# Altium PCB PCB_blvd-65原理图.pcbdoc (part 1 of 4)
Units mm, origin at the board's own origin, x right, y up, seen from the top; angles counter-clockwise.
Board outline 317.5 x 107.96 mm, 2 copper layers (Top Layer, Bottom Layer); 180 components, 111 nets, 404 pads, 231 vias.
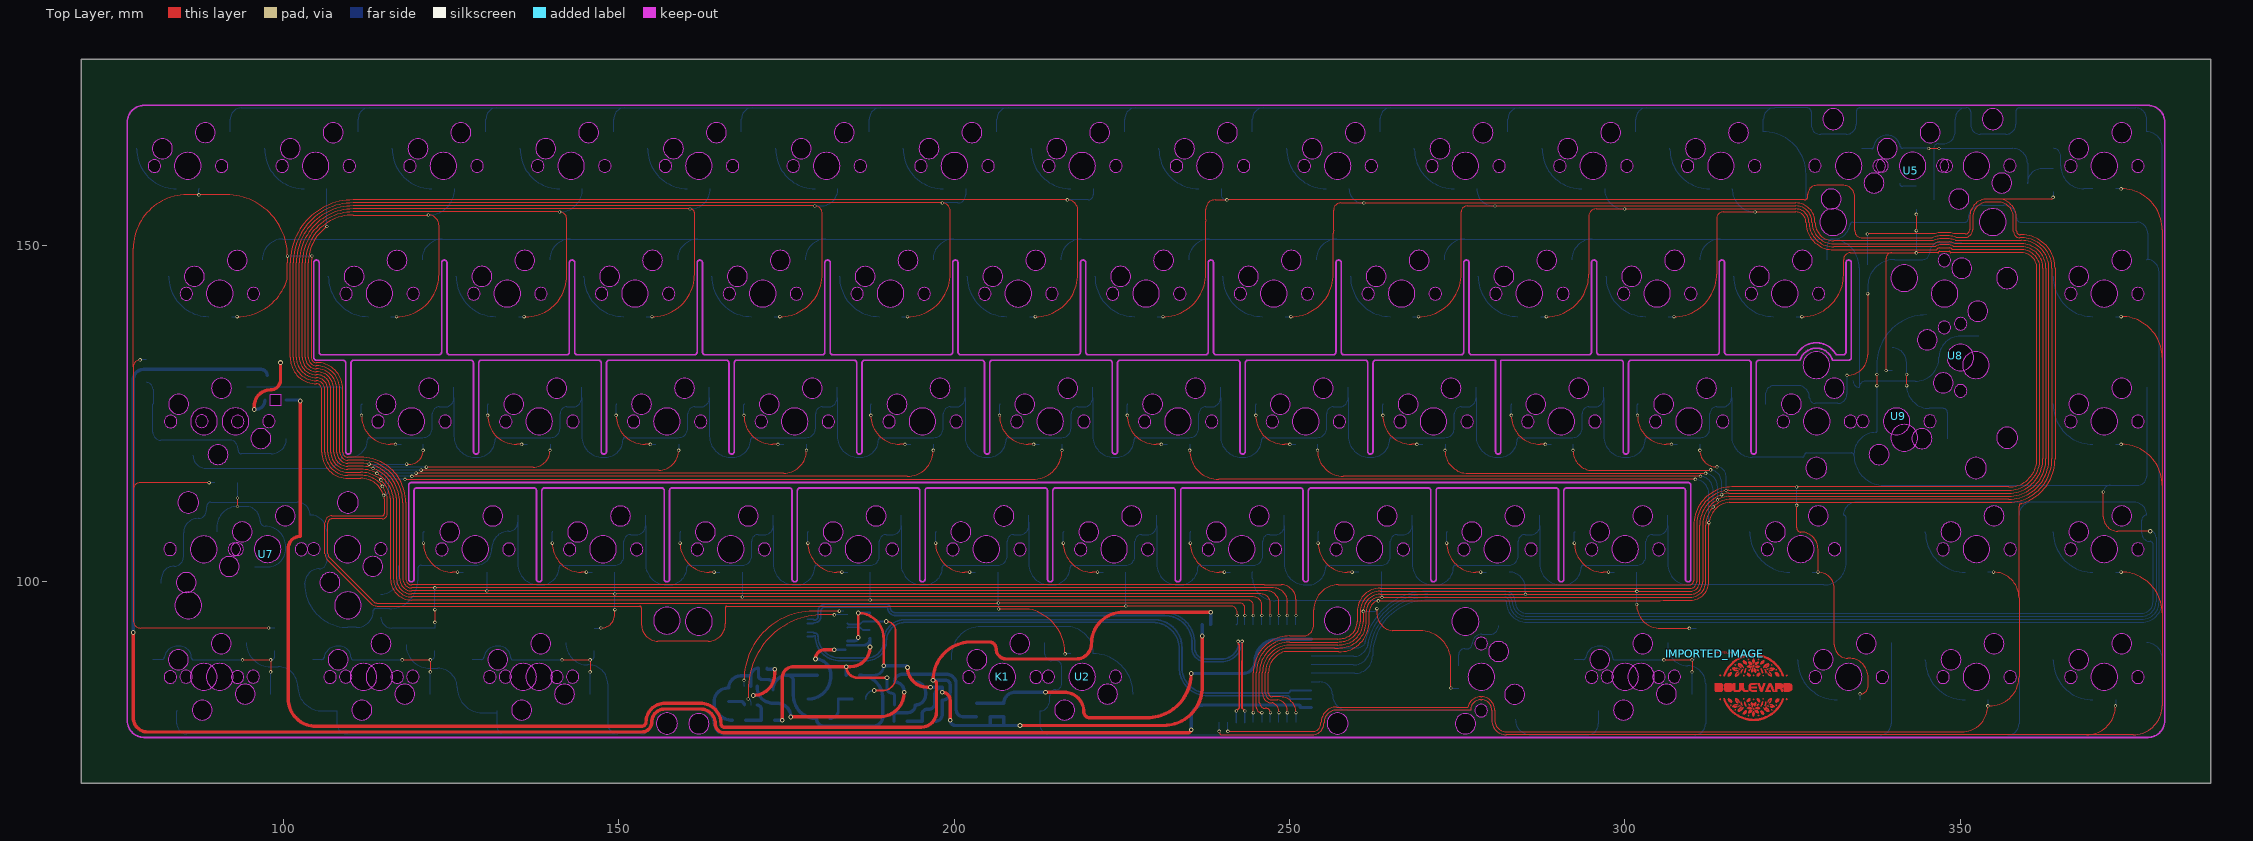
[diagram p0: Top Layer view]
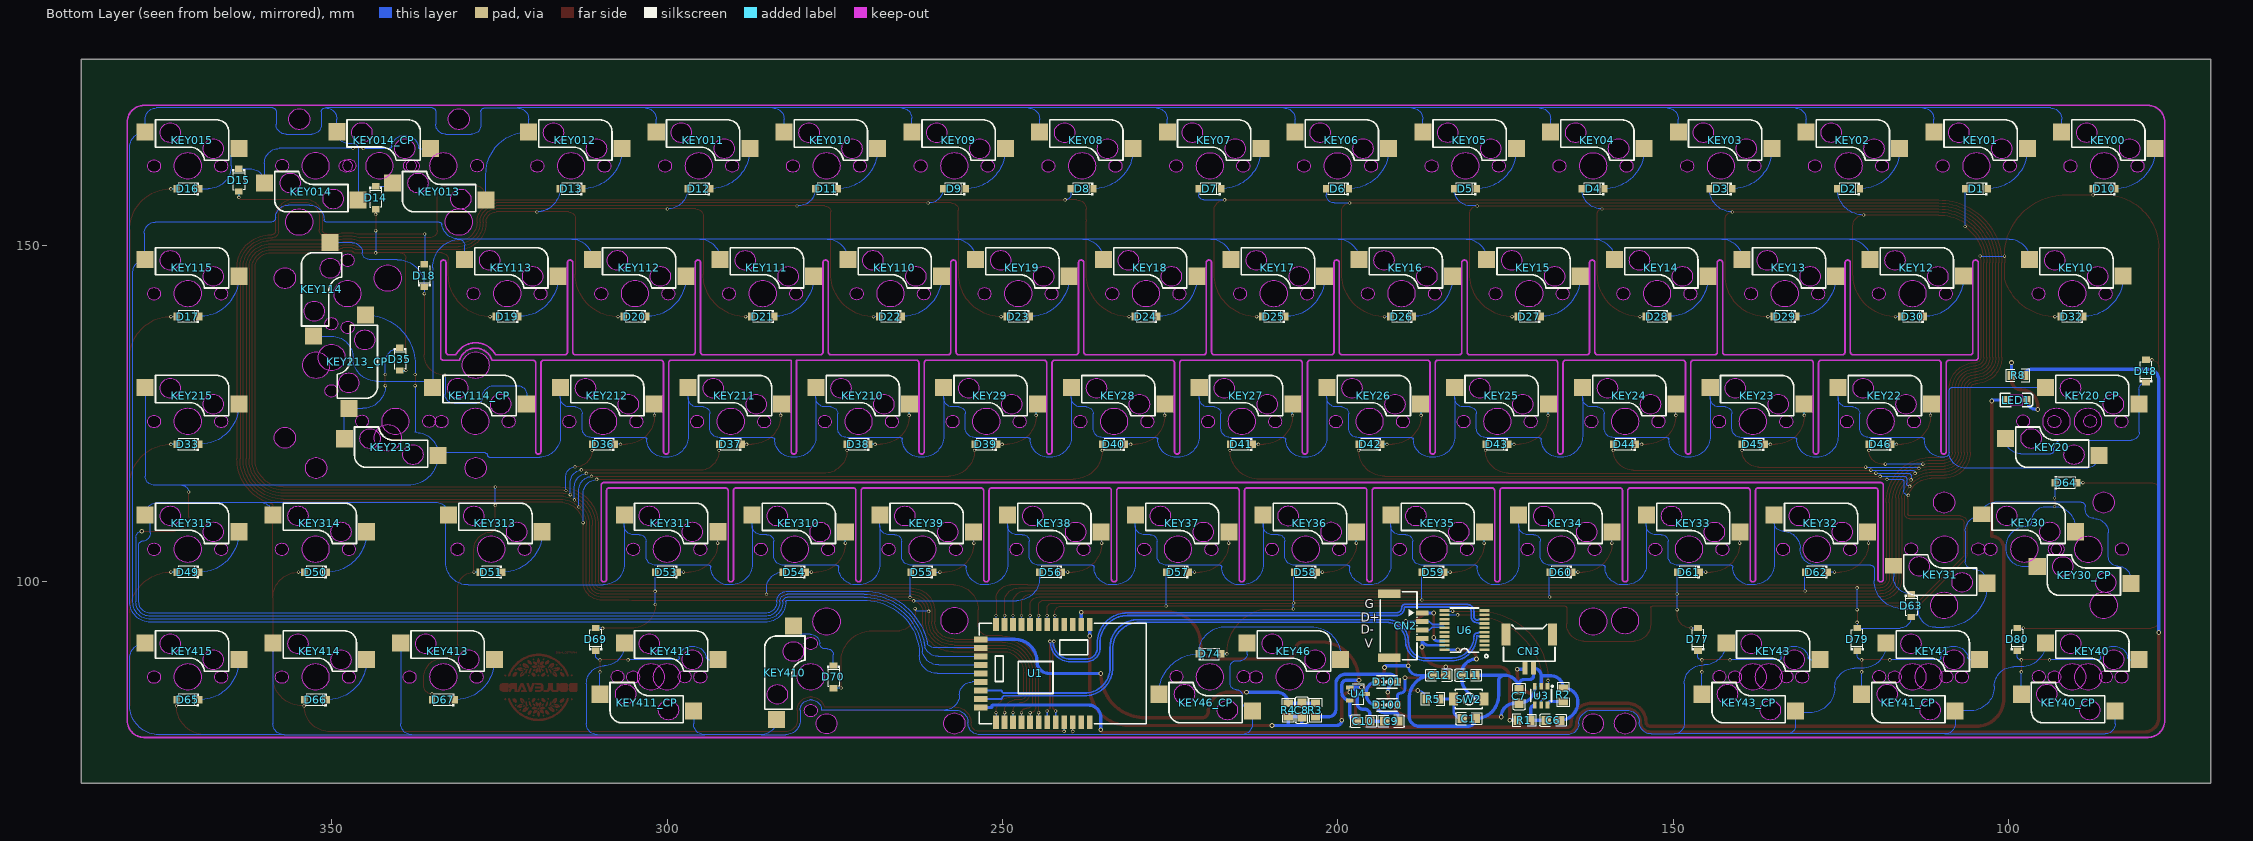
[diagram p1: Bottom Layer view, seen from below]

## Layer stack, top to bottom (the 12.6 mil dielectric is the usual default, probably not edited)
Top Layer: signal copper (thickness not stored)
Dielectric: dielectric 0.32, FR-4, Dk 4.8
Bottom Layer: signal copper (thickness not stored)

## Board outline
387.35,69.85 69.85,69.85 69.85,177.805 387.35,177.805

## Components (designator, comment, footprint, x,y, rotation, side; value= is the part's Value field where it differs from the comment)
C1 "47pF" C0805 180.467,79.502 r0 bottom
C6 "1uF" C0805 167.894,79.248 r0 bottom
C7 "10uF" C0805 172.974,82.804 r270 bottom
C8 "10nF" C0805 205.359,80.772 r270 bottom
C9 "1uF" C0805 192.024,79.121 r180 bottom
C10 "1uF" C0805 196.215,79.121 r0 bottom
C11 "100nF" C0805 180.594,85.979 r0 bottom
C12 "100nF" C0805 184.912,85.979 r180 bottom
CN2 "537800470" CONN-TH_4P-P1.25_537800470 189.865,93.345 r270 bottom
CN3 "537800270" CONN-SMD_2P-P1.25_53780-0X70 171.45,89.535 r0 bottom
D1 "1N4148W_C115103" SOD-123_L2.8-W1.8-LS3.7-RD 104.775,158.496 r0 bottom
D2 "1N4148W_C115103" SOD-123_L2.8-W1.8-LS3.7-RD 123.825,158.496 r0 bottom
D3 "1N4148W_C115103" SOD-123_L2.8-W1.8-LS3.7-RD 142.875,158.496 r0 bottom
D4 "1N4148W_C115103" SOD-123_L2.8-W1.8-LS3.7-RD 161.925,158.496 r0 bottom
D5 "1N4148W_C115103" SOD-123_L2.8-W1.8-LS3.7-RD 180.975,158.496 r0 bottom
D6 "1N4148W_C115103" SOD-123_L2.8-W1.8-LS3.7-RD 200.025,158.496 r0 bottom
D7 "1N4148W_C115103" SOD-123_L2.8-W1.8-LS3.7-RD 219.075,158.496 r0 bottom
D8 "1N4148W_C115103" SOD-123_L2.8-W1.8-LS3.7-RD 238.125,158.496 r0 bottom
D9 "1N4148W_C115103" SOD-123_L2.8-W1.8-LS3.7-RD 257.175,158.496 r0 bottom
D10 "1N4148W_C115103" SOD-123_L2.8-W1.8-LS3.7-RD 85.725,158.496 r0 bottom
D11 "1N4148W_C115103" SOD-123_L2.8-W1.8-LS3.7-RD 276.225,158.496 r0 bottom
D12 "1N4148W_C115103" SOD-123_L2.8-W1.8-LS3.7-RD 295.275,158.496 r0 bottom
D13 "1N4148W_C115103" SOD-123_L2.8-W1.8-LS3.7-RD 314.325,158.496 r0 bottom
D14 "1N4148W_C115103" SOD-123_L2.8-W1.8-LS3.7-RD 343.463,157.164 r270 bottom
D15 "1N4148W_C115103" SOD-123_L2.8-W1.8-LS3.7-RD 363.874,159.791 r270 bottom
D16 "1N4148W_C115103" SOD-123_L2.8-W1.8-LS3.7-RD 371.475,158.496 r0 bottom
D17 "1N4148W_C115103" SOD-123_L2.8-W1.8-LS3.7-RD 371.475,139.446 r0 bottom
D18 "1N4148W_C115103" SOD-123_L2.8-W1.8-LS3.7-RD 336.207,145.574 r90 bottom
D19 "1N4148W_C115103" SOD-123_L2.8-W1.8-LS3.7-RD 323.85,139.446 r0 bottom
D20 "1N4148W_C115103" SOD-123_L2.8-W1.8-LS3.7-RD 304.8,139.446 r0 bottom
D21 "1N4148W_C115103" SOD-123_L2.8-W1.8-LS3.7-RD 285.75,139.446 r0 bottom
D22 "1N4148W_C115103" SOD-123_L2.8-W1.8-LS3.7-RD 266.7,139.446 r0 bottom
D23 "1N4148W_C115103" SOD-123_L2.8-W1.8-LS3.7-RD 247.65,139.446 r0 bottom
D24 "1N4148W_C115103" SOD-123_L2.8-W1.8-LS3.7-RD 228.6,139.446 r0 bottom
D25 "1N4148W_C115103" SOD-123_L2.8-W1.8-LS3.7-RD 209.55,139.446 r0 bottom
D26 "1N4148W_C115103" SOD-123_L2.8-W1.8-LS3.7-RD 190.5,139.446 r0 bottom
D27 "1N4148W_C115103" SOD-123_L2.8-W1.8-LS3.7-RD 171.45,139.446 r0 bottom
D28 "1N4148W_C115103" SOD-123_L2.8-W1.8-LS3.7-RD 152.4,139.446 r0 bottom
D29 "1N4148W_C115103" SOD-123_L2.8-W1.8-LS3.7-RD 133.35,139.446 r0 bottom
D30 "1N4148W_C115103" SOD-123_L2.8-W1.8-LS3.7-RD 114.3,139.446 r0 bottom
D32 "1N4148W_C115103" SOD-123_L2.8-W1.8-LS3.7-RD 90.551,139.446 r0 bottom
D33 "1N4148W_C115103" SOD-123_L2.8-W1.8-LS3.7-RD 371.475,120.396 r0 bottom
D35 "1N4148W_C115103" SOD-123_L2.8-W1.8-LS3.7-RD 339.852,133.096 r270 bottom
D36 "1N4148W_C115103" SOD-123_L2.8-W1.8-LS3.7-RD 309.499,120.396 r0 bottom
D37 "1N4148W_C115103" SOD-123_L2.8-W1.8-LS3.7-RD 290.576,120.396 r0 bottom
D38 "1N4148W_C115103" SOD-123_L2.8-W1.8-LS3.7-RD 271.526,120.396 r0 bottom
D39 "1N4148W_C115103" SOD-123_L2.8-W1.8-LS3.7-RD 252.476,120.396 r0 bottom
D40 "1N4148W_C115103" SOD-123_L2.8-W1.8-LS3.7-RD 233.426,120.396 r0 bottom
D41 "1N4148W_C115103" SOD-123_L2.8-W1.8-LS3.7-RD 214.376,120.396 r0 bottom
D42 "1N4148W_C115103" SOD-123_L2.8-W1.8-LS3.7-RD 195.199,120.396 r0 bottom
D43 "1N4148W_C115103" SOD-123_L2.8-W1.8-LS3.7-RD 176.276,120.396 r0 bottom
D44 "1N4148W_C115103" SOD-123_L2.8-W1.8-LS3.7-RD 157.226,120.396 r0 bottom
D45 "1N4148W_C115103" SOD-123_L2.8-W1.8-LS3.7-RD 138.049,120.396 r0 bottom
D46 "1N4148W_C115103" SOD-123_L2.8-W1.8-LS3.7-RD 119.126,120.396 r0 bottom
D48 "1N4148W_C115103" SOD-123_L2.8-W1.8-LS3.7-RD 79.502,131.318 r90 bottom
D49 "1N4148W_C115103" SOD-123_L2.8-W1.8-LS3.7-RD 371.475,101.346 r0 bottom
D50 "1N4148W_C115103" SOD-123_L2.8-W1.8-LS3.7-RD 352.425,101.346 r0 bottom
D51 "1N4148W_C115103" SOD-123_L2.8-W1.8-LS3.7-RD 326.263,101.346 r0 bottom
D53 "1N4148W_C115103" SOD-123_L2.8-W1.8-LS3.7-RD 300.101,101.346 r0 bottom
D54 "1N4148W_C115103" SOD-123_L2.8-W1.8-LS3.7-RD 281.051,101.346 r0 bottom
D55 "1N4148W_C115103" SOD-123_L2.8-W1.8-LS3.7-RD 262.001,101.346 r0 bottom
D56 "1N4148W_C115103" SOD-123_L2.8-W1.8-LS3.7-RD 242.824,101.346 r0 bottom
D57 "1N4148W_C115103" SOD-123_L2.8-W1.8-LS3.7-RD 223.901,101.346 r0 bottom
D58 "1N4148W_C115103" SOD-123_L2.8-W1.8-LS3.7-RD 204.846,101.346 r0 bottom
D59 "1N4148W_C115103" SOD-123_L2.8-W1.8-LS3.7-RD 185.796,101.346 r0 bottom
D60 "1N4148W_C115103" SOD-123_L2.8-W1.8-LS3.7-RD 166.746,101.346 r0 bottom
D61 "1N4148W_C115103" SOD-123_L2.8-W1.8-LS3.7-RD 147.696,101.346 r0 bottom
D62 "1N4148W_C115103" SOD-123_L2.8-W1.8-LS3.7-RD 128.646,101.346 r0 bottom
D63 "1N4148W_C115103" SOD-123_L2.8-W1.8-LS3.7-RD 114.497,96.344 r270 bottom
D64 "1N4148W_C115103" SOD-123_L2.8-W1.8-LS3.7-RD 91.44,114.681 r180 bottom
D65 "1N4148W_C115103" SOD-123_L2.8-W1.8-LS3.7-RD 371.475,82.296 r0 bottom
D66 "1N4148W_C115103" SOD-123_L2.8-W1.8-LS3.7-RD 352.425,82.296 r0 bottom
D67 "1N4148W_C115103" SOD-123_L2.8-W1.8-LS3.7-RD 333.375,82.296 r0 bottom
D69 "1N4148W_C115103" SOD-123_L2.8-W1.8-LS3.7-RD 310.642,91.313 r90 bottom
D70 "1N4148W_C115103" SOD-123_L2.8-W1.8-LS3.7-RD 275.209,85.725 r270 bottom
D74 "1N4148W_C115103" SOD-123_L2.8-W1.8-LS3.7-RD 219.075,89.154 r180 bottom
D77 "1N4148W_C115103" SOD-123_L2.8-W1.8-LS3.7-RD 146.304,91.313 r90 bottom
D79 "1N4148W_C115103" SOD-123_L2.8-W1.8-LS3.7-RD 122.555,91.313 r90 bottom
D80 "1N4148W_C115103" SOD-123_L2.8-W1.8-LS3.7-RD 98.679,91.313 r90 bottom
D100 "B5819WL" SOD-123F_L2.8-W1.8-LS3.7-RD 192.659,81.534 r180 bottom
D101 "B5819WL" SOD-123F_L2.8-W1.8-LS3.7-RD 192.659,84.963 r180 bottom
IMPORTED_IMAGE "IMPORTED_IMAGE" IMPORTED_IMAGE#1 313.437,89.153 r0 top
IMPORTED_IMAGE "IMPORTED_IMAGE" IMPORTED_IMAGE#2 313.437,89.153 r0 top
K1 "6.25U卫星轴 COPY" 6.25U卫星轴 207.167,85.726 r180 top
KEY00 "KEY00" 凯华轴座无灯#1 85.725,161.926 r0 top
KEY01 "KEY01" 凯华轴座无灯#1 104.775,161.926 r0 top
KEY02 "凯华轴座无灯 COPY" 凯华轴座无灯#1 123.825,161.926 r0 top
KEY03 "凯华轴座无灯 COPY" 凯华轴座无灯#1 142.875,161.926 r0 top
KEY04 "凯华轴座无灯 COPY" 凯华轴座无灯#1 161.925,161.926 r0 top
KEY05 "凯华轴座无灯 COPY" 凯华轴座无灯#1 180.974,161.926 r0 top
KEY06 "凯华轴座无灯 COPY" 凯华轴座无灯#1 200.023,161.926 r0 top
KEY07 "凯华轴座无灯 COPY" 凯华轴座无灯#1 219.075,161.926 r0 top
KEY08 "凯华轴座无灯 COPY" 凯华轴座无灯#1 238.125,161.926 r0 top
KEY09 "凯华轴座无灯 COPY" 凯华轴座无灯#1 257.175,161.926 r0 top
KEY010 "凯华轴座无灯 COPY" 凯华轴座无灯#1 276.225,161.925 r0 top
KEY10 "KEY00" 凯华轴座无灯#1 90.488,142.876 r0 top
KEY011 "凯华轴座无灯 COPY" 凯华轴座无灯#1 295.275,161.926 r0 top
KEY012 "凯华轴座无灯 COPY" 凯华轴座无灯#1 314.325,161.925 r0 top
KEY12 "凯华轴座无灯 COPY" 凯华轴座无灯#1 114.3,142.876 r0 top
KEY013 "凯华轴座无灯 COPY" 凯华轴座无灯#1 333.375,161.925 r180 top
KEY13 "凯华轴座无灯 COPY" 凯华轴座无灯#1 133.35,142.875 r0 top
KEY14 "凯华轴座无灯 COPY" 凯华轴座无灯#1 152.4,142.875 r0 top
KEY014 "凯华轴座无灯 COPY" 凯华轴座无灯#1 352.425,161.93 r180 top
KEY014_CP "凯华轴座无灯 COPY" 凯华轴座无灯#1 342.9,161.93 r0 top
KEY15 "凯华轴座无灯 COPY" 凯华轴座无灯#1 171.45,142.875 r0 top
KEY015 "凯华轴座无灯 COPY" 凯华轴座无灯#1 371.475,161.926 r0 top
KEY16 "凯华轴座无灯 COPY" 凯华轴座无灯#1 190.5,142.875 r0 top
KEY17 "凯华轴座无灯 COPY" 凯华轴座无灯#1 209.55,142.875 r0 top
KEY18 "凯华轴座无灯 COPY" 凯华轴座无灯#1 228.6,142.875 r0 top
KEY19 "凯华轴座无灯 COPY" 凯华轴座无灯#1 247.65,142.875 r0 top
KEY20 "KEY00" 凯华轴座无灯#1 92.837,123.825 r180 top
KEY20_CP "KEY00" 凯华轴座无灯#1 88.138,123.825 r0 top
KEY22 "凯华轴座无灯 COPY" 凯华轴座无灯#1 119.063,123.815 r0 top
KEY23 "凯华轴座无灯 COPY" 凯华轴座无灯#1 138.113,123.815 r0 top
KEY24 "凯华轴座无灯 COPY" 凯华轴座无灯#1 157.163,123.815 r0 top
KEY25 "凯华轴座无灯 COPY" 凯华轴座无灯#1 176.213,123.815 r0 top
KEY26 "凯华轴座无灯 COPY" 凯华轴座无灯#1 195.263,123.815 r0 top
KEY27 "凯华轴座无灯 COPY" 凯华轴座无灯#1 214.313,123.815 r0 top
KEY28 "凯华轴座无灯 COPY" 凯华轴座无灯#1 233.363,123.815 r0 top
KEY29 "凯华轴座无灯 COPY" 凯华轴座无灯#1 252.413,123.815 r0 top
KEY30 "KEY00" 凯华轴座无灯#2 97.631,104.776 r0 top
KEY30_CP "KEY00" 凯华轴座无灯#1 88.106,104.745 r180 top
KEY31 "KEY01" 凯华轴座无灯#3 109.533,104.765 r180 top
KEY32 "凯华轴座无灯 COPY" 凯华轴座无灯#1 128.583,104.765 r0 top
KEY33 "凯华轴座无灯 COPY" 凯华轴座无灯#1 147.633,104.765 r0 top
KEY34 "凯华轴座无灯 COPY" 凯华轴座无灯#1 166.683,104.765 r0 top
KEY35 "凯华轴座无灯 COPY" 凯华轴座无灯#1 185.733,104.765 r0 top
KEY36 "凯华轴座无灯 COPY" 凯华轴座无灯#1 204.783,104.765 r0 top
KEY37 "凯华轴座无灯 COPY" 凯华轴座无灯#1 223.833,104.765 r0 top
KEY38 "凯华轴座无灯 COPY" 凯华轴座无灯#1 242.883,104.765 r0 top
KEY39 "凯华轴座无灯 COPY" 凯华轴座无灯#1 261.933,104.765 r0 top
KEY40 "KEY00" 凯华轴座无灯#1 88.106,85.726 r0 top
KEY40_CP "KEY00" 凯华轴座无灯#1 90.488,85.726 r180 top
KEY41 "KEY01" 凯华轴座无灯#1 111.917,85.726 r0 top
KEY41_CP "KEY01" 凯华轴座无灯#1 114.3,85.726 r180 top
KEY43 "凯华轴座无灯 COPY" 凯华轴座无灯#1 135.731,85.726 r0 top
KEY43_CP "凯华轴座无灯 COPY" 凯华轴座无灯#1 138.113,85.726 r180 top
KEY46 "凯华轴座无灯 COPY" 凯华轴座无灯#1 207.167,85.726 r0 top
KEY46_CP "凯华轴座无灯 COPY" 凯华轴座无灯#1 219.075,85.726 r180 top
KEY110 "凯华轴座无灯 COPY" 凯华轴座无灯#1 266.7,142.875 r0 top
KEY111 "凯华轴座无灯 COPY" 凯华轴座无灯#1 285.75,142.875 r0 top
KEY112 "凯华轴座无灯 COPY" 凯华轴座无灯#1 304.8,142.875 r0 top
KEY113 "凯华轴座无灯 COPY" 凯华轴座无灯#1 323.85,142.875 r0 top
KEY114 "凯华轴座无灯 COPY" 凯华轴座无灯#4 347.665,142.872 r270 top
KEY114_CP "凯华轴座无灯 COPY" 凯华轴座无灯#1 328.612,123.825 r0 top
KEY115 "凯华轴座无灯 COPY" 凯华轴座无灯#1 371.475,142.875 r0 top
KEY210 "凯华轴座无灯 COPY" 凯华轴座无灯#1 271.463,123.815 r0 top
KEY211 "凯华轴座无灯 COPY" 凯华轴座无灯#1 290.513,123.815 r0 top
KEY212 "凯华轴座无灯 COPY" 凯华轴座无灯#1 309.563,123.815 r0 top
KEY213 "凯华轴座无灯 COPY" 凯华轴座无灯#1 340.519,123.822 r180 top
KEY213_CP "凯华轴座无灯 COPY" 凯华轴座无灯#4 350.044,133.347 r90 top
KEY215 "凯华轴座无灯 COPY" 凯华轴座无灯#1 371.475,123.825 r0 top
KEY310 "凯华轴座无灯 COPY" 凯华轴座无灯#1 280.983,104.765 r0 top
KEY311 "凯华轴座无灯 COPY" 凯华轴座无灯#1 300.037,104.776 r0 top
KEY313 "凯华轴座无灯 COPY" 凯华轴座无灯#1 326.232,104.775 r0 top
KEY314 "凯华轴座无灯 COPY" 凯华轴座无灯#1 352.425,104.775 r0 top
KEY315 "凯华轴座无灯 COPY" 凯华轴座无灯#1 371.475,104.775 r0 top
KEY410 "凯华轴座无灯 COPY" 凯华轴座无灯#4 278.606,85.726 r270 top
KEY411 "凯华轴座无灯 COPY" 凯华轴座无灯#1 300.037,85.726 r0 top
KEY411_CP "凯华轴座无灯 COPY" 凯华轴座无灯#1 302.417,85.726 r180 top
KEY413 "凯华轴座无灯 COPY" 凯华轴座无灯#1 333.375,85.725 r0 top
KEY414 "凯华轴座无灯 COPY" 凯华轴座无灯#1 352.425,85.725 r0 top
KEY415 "凯华轴座无灯 COPY" 凯华轴座无灯#1 371.475,85.725 r0 top
LED1 "MHT151UBCT" LED-SMD_L3.2-W1.3-RD-EH2.1 98.806,127 r0 bottom
R1 "1Ω" R0805 172.212,79.248 r0 bottom
R2 "4.7K" R0805 166.37,83.058 r90 bottom
R3 "10MΩ" R0805 203.327,80.772 r270 bottom
R4 "2.2MΩ" R0805 207.391,80.772 r270 bottom
R5 "10K" R0805 185.801,82.423 r180 bottom
R8 "15Ω" R0805 98.552,130.683 r180 bottom
SW2 "TS-1088R-02026" SW-SMD_L3.9-W3.0-P4.45 180.467,82.423 r180 bottom
U1 "NRF52832 RF-BM-ND04" BULETM-SMD_NRF52832 245.11,86.233 r270 bottom
U2 "PCB卫星轴-7U COPY" PCB卫星轴-7U 219.075,85.726 r0 top
U3 "TP4057" SOT-23-6_L2.9-W1.6-P0.95-LS2.8-BR 169.672,82.931 r90 bottom
U4 "XC6206P332MR" SOT-23-3_L2.9-W1.6-P1.90-LS2.8-BR 196.977,83.185 r0 bottom
U5 "PCB卫星轴2U COPY" 卫星轴2U#1 342.631,161.183 r0 top
U6 "CH552T" TSSOP-20_L6.5-W4.4-P0.65-LS6.4-BL 181.102,92.71 r90 bottom
U7 "PCB卫星轴2U COPY" 卫星轴2U#1 97.362,104.029 r0 top
U8 "PCB卫星轴2U COPY" 卫星轴2U#2 349.297,133.617 r270 top
U9 "PCB卫星轴2U COPY" 卫星轴2U#1 340.788,124.569 r180 top

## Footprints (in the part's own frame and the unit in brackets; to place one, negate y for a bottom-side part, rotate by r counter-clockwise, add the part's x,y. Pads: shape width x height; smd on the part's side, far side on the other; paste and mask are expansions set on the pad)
6.25U卫星轴 [mm]
  Multi-Layer board cut-out: -51.575,6.95 -51.419,6.267 -50.982,5.719 -50.35,5.414 -49.649,5.414 -49.018,5.718 -48.581,6.266 -48.425,6.95 -48.425,6.95 -48.581,7.633 -49.018,8.181 -49.649,8.485 -50.35,8.485 -50.982,8.181 -51.419,7.633 -51.575,6.95
  Multi-Layer board cut-out: 48.425,6.95 48.581,6.267 49.018,5.719 49.649,5.414 50.35,5.414 50.982,5.718 51.419,6.266 51.575,6.95 51.575,6.95 51.419,7.633 50.982,8.181 50.35,8.485 49.649,8.485 49.018,8.181 48.581,7.633 48.425,6.95
  Multi-Layer board cut-out: -52,-8.389 -51.802,-9.257 -51.247,-9.953 -50.445,-10.339 -49.555,-10.339 -48.753,-9.953 -48.198,-9.257 -48,-8.389 -48,-8.389 -48.198,-7.521 -48.753,-6.826 -49.555,-6.439 -50.445,-6.439 -51.247,-6.825 -51.802,-7.521 -52,-8.389
  Multi-Layer board cut-out: 48,-8.389 48.198,-9.257 48.753,-9.953 49.555,-10.339 50.445,-10.339 51.247,-9.953 51.802,-9.257 52,-8.389 52,-8.389 51.802,-7.521 51.247,-6.826 50.445,-6.439 49.555,-6.439 48.753,-6.825 48.198,-7.521 48,-8.389
  Multi-Layer keep-out region: -51.575,6.95 -51.419,6.267 -50.982,5.719 -50.35,5.414 -49.649,5.414 -49.018,5.718 -48.581,6.266 -48.425,6.95 -48.425,6.95 -48.581,7.633 -49.018,8.181 -49.649,8.485 -50.35,8.485 -50.982,8.181 -51.419,7.633 -51.575,6.95
  Multi-Layer keep-out region: 48.425,6.95 48.581,6.267 49.018,5.719 49.649,5.414 50.35,5.414 50.982,5.718 51.419,6.266 51.575,6.95 51.575,6.95 51.419,7.633 50.982,8.181 50.35,8.485 49.649,8.485 49.018,8.181 48.581,7.633 48.425,6.95
  Multi-Layer keep-out region: -52,-8.389 -51.802,-9.257 -51.247,-9.953 -50.445,-10.339 -49.555,-10.339 -48.753,-9.953 -48.198,-9.257 -48,-8.389 -48,-8.389 -48.198,-7.521 -48.753,-6.826 -49.555,-6.439 -50.445,-6.439 -51.247,-6.825 -51.802,-7.521 -52,-8.389
  Multi-Layer keep-out region: 48,-8.389 48.198,-9.257 48.753,-9.953 49.555,-10.339 50.445,-10.339 51.247,-9.953 51.802,-9.257 52,-8.389 52,-8.389 51.802,-7.521 51.247,-6.826 50.445,-6.439 49.555,-6.439 48.753,-6.825 48.198,-7.521 48,-8.389
BULETM-SMD_NRF52832 [mm]
  rect 2x0.85 smd: 1(-7.3,8.117) 2(-7.3,6.847) 3(-7.3,5.577) 4(-7.3,4.307) 5(-7.3,3.037) 6(-7.3,1.767) 7(-7.3,0.497) 8(-7.3,-0.773) 9(-7.3,-2.043) 10(-7.3,-3.313) 11(-7.3,-4.583) 12(-7.3,-5.853) 22(7.3,-5.853) 23(7.3,-4.583) 24(7.3,-3.313) 25(7.3,-2.043) 26(7.3,-0.773) 27(7.3,0.497) 28(7.3,1.767) 29(7.3,3.037) 30(7.3,4.307) 31(7.3,5.577) 32(7.3,6.847) 33(7.3,8.117)
  rect 0.85x2 smd: 13(-5.08,-8.117) 14(-3.81,-8.117) 15(-2.54,-8.117) 16(-1.27,-8.117) 17(0,-8.117) 18(1.27,-8.117) 19(2.54,-8.117) 20(3.81,-8.117) 21(5.08,-8.117)
  silkscreen extent -7.49,-8.36 7.49,16.53
C0805 [mm]
  rect 1.41x1.35 smd: 1(-1,0) 2(1,0)
  silkscreen extent -1.96,-0.9 1.96,0.9
CONN-SMD_2P-P1.25_53780-0X70 [mm]
  rect 0.8x1.9 smd: 1(-0.621,2.508) 2(0.631,2.508)
  rect 1.3x3.35 smd: 3(3.47,-2.508) 4(-3.47,-2.508)
  silkscreen extent -3.83,-4 3.83,1.49
CONN-TH_4P-P1.25_537800470 [mm]
  rect 0.8x1.9 smd: 1(-1.905,2.438) 2(-0.635,2.438) 3(0.635,2.438) 4(1.905,2.438)
  rect 1.3x3.35 smd: 5(4.755,-2.437) 6(-4.755,-2.437)
  silkscreen extent -5.08,-3.82 5.08,1.68
IMPORTED_IMAGE#1 [mm]
  Top Layer region: 5.77,-9.999 5.544,-9.996 5.387,-9.987 5.06,-9.942 4.832,-9.898 4.777,-9.884 4.717,-9.87 4.663,-9.857 4.625,-9.847 4.58,-9.834 4.51,-9.815 4.315,-9.757 4.117,-9.688 3.919,-9.607 3.72,-9.516 3.523,-9.415 3.329,-9.305 3.139,-9.186 2.953,-9.059 2.807,-8.95 2.666,-8.836 2.529,-8.716 2.397,-8.592 2.27,-8.463 2.148,-8.33 2.032,-8.193 1.922,-8.053 1.817,-7.909 1.719,-7.763 1.628,-7.614 1.543,-7.462 1.465,-7.309 1.395,-7.154 1.332,-6.998 1.276,-6.84 1.256,-6.705 1.317,-6.637 1.449,-6.64 1.549,-6.816 1.64,-7.037 1.758,-7.278 1.89,-7.512 2.021,-7.712 2.062,-7.769 2.096,-7.817 2.17,-7.914 2.264,-8.027 2.373,-8.15 2.49,-8.277 2.61,-8.4 2.725,-8.513 2.829,-8.61 2.917,-8.683 3.115,-8.83 3.317,-8.966 3.52,-9.091 3.724,-9.203 3.927,-9.303 4.128,-9.39 4.326,-9.463 4.519,-9.521 4.544,-9.528 4.57,-9.535 4.776,-9.586 4.985,-9.629 5.194,-9.663 5.399,-9.688 5.596,-9.704 5.784,-9.711 5.957,-9.708 6.113,-9.694 6.2,-9.683 6.292,-9.673 6.479,-9.647 6.636,-9.617 6.706,-9.599 6.783,-9.581 6.923,-9.544 7.065,-9.501 7.211,-9.45 7.357,-9.394 7.504,-9.332 7.651,-9.264 7.796,-9.192 7.939,-9.116 8.078,-9.036 8.214,-8.953 8.344,-8.868 8.468,-8.78 8.585,-8.691 8.695,-8.601 8.795,-8.511 8.886,-8.42 8.929,-8.375 9.006,-8.295 9.155,-8.133 9.296,-7.963 9.429,-7.788 9.553,-7.607 9.668,-7.421 9.774,-7.231 9.87,-7.038 9.955,-6.841 10.042,-6.657 10.124,-6.623 10.21,-6.642 10.248,-6.704 10.238,-6.814 10.182,-6.977 10.148,-7.06 10.108,-7.156 10.005,-7.378 9.873,-7.621 9.729,-7.854 9.591,-8.046 9.537,-8.115 9.497,-8.167 9.473,-8.197 9.46,-8.212 9.431,-8.245 9.369,-8.318 9.269,-8.432 9.165,-8.542 9.056,-8.65 8.943,-8.754 8.826,-8.855 8.706,-8.953 8.581,-9.047 8.453,-9.137 8.321,-9.224 8.186,-9.307 8.048,-9.386 7.906,-9.461 7.762,-9.532 7.615,-9.599 7.466,-9.662 7.314,-9.72 7.265,-9.738 7.217,-9.755 7.015,-9.82 6.829,-9.87 6.787,-9.879 6.724,-9.894 6.498,-9.939 6.264,-9.972 6.211,-9.978 6.14,-9.988 5.993,-9.996
  Top Layer region: 5.886,-9.219 5.747,-9.348 5.642,-9.269 5.571,-9.121 5.548,-8.951 5.586,-8.805 5.643,-8.71 5.682,-8.628 5.708,-8.574 5.727,-8.541 5.769,-8.526 5.809,-8.589 5.841,-8.653 5.895,-8.75 5.966,-8.869 5.966,-8.952
  Top Layer region: 6.494,-9.297 6.397,-9.232 6.391,-9.157 6.452,-9.093 6.582,-9.113 6.595,-9.245
  Top Layer region: 5.067,-9.274 4.931,-9.269 4.898,-9.141 4.916,-9.119 4.941,-9.097 5.089,-9.124
  Top Layer region: 7.29,-9.093 7.151,-9.091 7,-9.016 6.871,-8.891 6.799,-8.741 6.772,-8.545 6.811,-8.452 6.905,-8.423 7.031,-8.45 7.163,-8.522 7.271,-8.629 7.358,-8.901 hole: 3204467.29,803299.469 3205498.859,802538.344 3205498.859,802538.344 3205664.93,803452.604 3205664.93,803452.604 3204513.833,804823.082 3204513.833,804823.082 3203917.787,805031.667 3203917.787,805031.667 3203752.121,804528.547 3203752.121,804528.547 3204467.29,803299.469
  Top Layer region: 4.662,-8.833 4.396,-9.074 4.156,-9.038 4.137,-8.877 4.204,-8.696 4.333,-8.536 4.499,-8.441 4.65,-8.43 4.73,-8.497 4.735,-8.634 hole: 3177686.771,802611.918 3178805.897,803453.136 3178805.897,803453.136 3179417.179,804790.365 3179417.179,804790.365 3178879.991,804973.307 3178879.991,804973.307 3177833.36,803979.782 3177833.36,803979.782 3177279.43,802951.482 3177279.43,802951.482 3177686.771,802611.918
  Top Layer region: 5.048,-8.863 4.934,-8.844 4.941,-8.743 4.988,-8.604 5.052,-8.509 5.148,-8.441 5.291,-8.387 5.366,-8.364 5.41,-8.35 5.474,-8.342 5.509,-8.367 5.527,-8.397 5.553,-8.431 5.585,-8.468 5.539,-8.565 5.452,-8.707 5.345,-8.801 5.213,-8.852
  Top Layer region: 6.453,-8.863 6.289,-8.851 6.153,-8.797 6.043,-8.7 5.957,-8.559 5.927,-8.475 5.952,-8.429 5.978,-8.4 6.004,-8.367 6.048,-8.335 6.195,-8.378 6.349,-8.441 6.452,-8.517 6.518,-8.621 6.559,-8.766 6.555,-8.845
  Top Layer region: 3.73,-8.607 3.493,-8.649 3.412,-8.548 3.431,-8.355 3.524,-8.172 3.676,-8.018 3.871,-7.917 3.976,-7.904 3.999,-7.946 3.99,-7.961 3.962,-7.994 3.899,-8.061 3.783,-8.182 3.635,-8.363 3.644,-8.431 3.73,-8.394 3.866,-8.286 4.017,-8.137 4.151,-7.976 4.243,-7.931 4.287,-8.005 4.23,-8.189 4.107,-8.362 3.935,-8.507
  Top Layer region: 8.078,-8.598 8.006,-8.642 7.876,-8.638 7.715,-8.59 7.548,-8.505 7.396,-8.37 7.278,-8.205 7.218,-8.051 7.24,-7.951 7.307,-7.933 7.382,-8.014 7.483,-8.131 7.632,-8.27 7.777,-8.385 7.867,-8.433 7.893,-8.416 7.871,-8.362 7.8,-8.272 7.678,-8.143 7.524,-7.974 7.504,-7.9 7.633,-7.914 7.799,-7.997 7.812,-8.007 7.823,-8.01 7.925,-8.084 8.022,-8.255 8.084,-8.451
  Top Layer region: 3.056,-8.463 2.943,-8.399 2.943,-8.33 2.99,-8.28 3.091,-8.28 3.135,-8.363
  Top Layer region: 8.562,-8.339 8.513,-8.451 8.386,-8.43 8.397,-8.298 8.429,-8.273 8.469,-8.268
  Top Layer region: 5.897,-8.256 5.752,-8.364 5.609,-8.261 5.606,-8.137 5.704,-8.041 5.869,-8.084
  Top Layer region: 6.574,-8.229 6.408,-8.283 6.197,-8.247 6.062,-8.167 6.057,-8.14 6.044,-8.097 6.086,-7.981 6.275,-7.9 6.388,-7.896 6.49,-7.91 6.587,-7.954 6.674,-8.007 6.761,-8.075 6.729,-8.125
  Top Layer region: 5.074,-8.277 4.855,-8.189 4.751,-8.072 4.853,-7.988 5.032,-7.908 5.195,-7.897 5.374,-7.957 5.468,-8.017 5.47,-8.089 5.46,-8.132 5.456,-8.159 5.31,-8.246
  Top Layer region: 2.896,-8.016 2.655,-7.972 2.571,-7.918 2.58,-7.847 2.605,-7.81 2.641,-7.755 2.769,-7.604 2.926,-7.514 2.97,-7.498 2.999,-7.486 3.026,-7.479 3.064,-7.475 3.358,-7.494 3.5,-7.566 3.49,-7.593 3.446,-7.615 3.345,-7.639 3.165,-7.672 2.887,-7.742 2.859,-7.812 2.938,-7.826 3.063,-7.817 3.313,-7.779 3.356,-7.807 3.303,-7.921 3.131,-7.995
  Top Layer region: 8.868,-7.96 8.645,-8.011 8.416,-8.002 8.233,-7.942 8.15,-7.84 8.163,-7.781 8.267,-7.789 8.576,-7.824 8.653,-7.773 8.622,-7.742 8.552,-7.716 8.424,-7.689 8.221,-7.657 7.997,-7.567 8.216,-7.477 8.405,-7.472 8.559,-7.502 8.769,-7.631 8.917,-7.828 8.939,-7.909
  Top Layer region: 5.572,-7.937 5.518,-7.877 5.458,-7.767 5.393,-7.565 5.374,-7.338 5.442,-7.191 5.453,-7.186 5.467,-7.184 5.567,-7.25 5.66,-7.33 5.675,-7.349 5.706,-7.384 5.75,-7.43 5.839,-7.34 5.987,-7.222 6.086,-7.208 6.134,-7.297 6.128,-7.489 5.959,-7.91 5.833,-7.758 5.81,-7.548 5.759,-7.474 5.707,-7.537 5.68,-7.742 5.671,-7.892 5.623,-7.93
  Top Layer region: 7,-7.75 6.877,-7.863 6.83,-7.856 6.816,-7.814 6.837,-7.711 6.894,-7.516 6.924,-7.419 6.949,-7.335 6.998,-7.191 7.042,-7.121 7.129,-7.093 7.188,-7.151 7.151,-7.346 7.091,-7.553 7.084,-7.568 7.082,-7.58
  Top Layer region: 4.676,-7.852 4.604,-7.86 4.487,-7.717 4.386,-7.475 4.332,-7.235 4.36,-7.102 4.441,-7.105 4.508,-7.195 4.542,-7.286 4.59,-7.459 4.604,-7.51 4.62,-7.56 4.635,-7.608 4.648,-7.652 4.661,-7.698 4.678,-7.752
  Top Layer region: 7.966,-7.854 7.842,-7.822 7.718,-7.776 7.704,-7.722 7.766,-7.678 7.885,-7.697 7.985,-7.757 7.996,-7.819
  Top Layer region: 3.53,-7.847 3.5,-7.799 3.561,-7.729 3.679,-7.678 3.75,-7.677 3.794,-7.721 3.796,-7.78 3.645,-7.831
  Top Layer region: 2.344,-7.771 2.247,-7.69 2.291,-7.574 2.363,-7.564 2.424,-7.594 2.431,-7.704
  Top Layer region: 4.151,-7.684 4.135,-7.769 3.982,-7.694 3.925,-7.619 3.86,-7.476 3.825,-7.27 3.848,-7.118 3.938,-7.117 3.995,-7.253 4.018,-7.384 4.044,-7.468 4.096,-7.585
  Top Layer region: 7.471,-7.746 7.36,-7.766 7.343,-7.735 7.393,-7.622 7.471,-7.433 7.518,-7.204 7.53,-7.166 7.554,-7.133 7.643,-7.107 7.679,-7.227 7.659,-7.429 7.58,-7.645
  Top Layer region: 6.264,-7.757 6.204,-7.723 6.235,-7.623 6.328,-7.506 6.455,-7.422 6.501,-7.409 6.546,-7.417 6.595,-7.485 6.54,-7.593 6.418,-7.698
  Top Layer region: 5.298,-7.727 5.187,-7.756 5.017,-7.663 4.941,-7.533 4.951,-7.434 5.041,-7.424 5.16,-7.495 5.261,-7.609
  Top Layer region: 9.226,-7.734 9.119,-7.754 9.066,-7.656 9.076,-7.605 9.114,-7.569 9.242,-7.599
  Top Layer region: 8.207,-7.326 8.017,-7.388 8.026,-7.3 8.235,-7.024 8.302,-6.848 8.269,-6.828 8.207,-6.867 8.106,-6.976 7.956,-7.163 7.856,-7.249 7.842,-7.121 7.883,-6.951 7.968,-6.811 8.098,-6.7 8.276,-6.617 8.441,-6.599 8.494,-6.721 8.482,-6.911 8.426,-7.082 8.333,-7.224
  Top Layer region: 3.509,-7.38 3.443,-7.384 3.329,-7.34 3.203,-7.257 3.084,-7.103 3.011,-6.906 2.996,-6.72 3.052,-6.6 3.118,-6.59 3.235,-6.624 3.419,-6.721 3.554,-6.848 3.637,-7.002 3.665,-7.18 3.657,-7.246 3.626,-7.251 3.56,-7.186 3.447,-7.046 3.259,-6.843 3.197,-6.882 3.226,-6.966 3.367,-7.156 3.446,-7.259 3.493,-7.321
  Top Layer region: 9.029,-7.31 8.953,-7.161 8.986,-6.986 9.07,-6.833 9.2,-6.713 9.368,-6.632 9.574,-6.66 9.575,-6.904 9.424,-7.146 9.215,-7.293 hole: 3225489.132,820441.361 3226908.333,821027.349 3226908.333,821027.349 3228001.255,822661.382 3228001.255,822661.382 3227931.602,822910.1 3227931.602,822910.1 3227730.881,822990.389 3227730.881,822990.389 3226281.221,821908.428 3226281.221,821908.428 3225489.132,820441.361
  Top Layer region: 2.465,-7.307 2.345,-7.301 2.206,-7.245 2.075,-7.147 1.925,-6.859 1.955,-6.623 2.07,-6.609 2.23,-6.673 2.389,-6.789 2.502,-6.933 2.543,-7.105 2.538,-7.257 hole: 3157523.127,820374.779 3157297.811,821486.239 3157297.811,821486.239 3155911.177,822830.149 3155911.177,822830.149 3155301.054,822982.637 3155301.054,822982.637 3155283.904,822436.231 3155283.904,822436.231 3156327.019,821105.264 3156327.019,821105.264 3157523.127,820374.779
  Top Layer region: 6.774,-7.002 6.665,-7.195 6.561,-7.177 6.454,-7.142 6.306,-7.02 6.225,-6.855 6.223,-6.701 6.315,-6.611 6.392,-6.61 6.472,-6.624 6.549,-6.659 6.61,-6.701 hole: 3198979.287,821830.209 3199622.115,821464.792 3199622.115,821464.792 3199988.137,821922.237 3199988.137,821922.237 3199280.067,822939.426 3199280.067,822939.426 3198615.716,823516.379 3198615.716,823516.379 3198230.577,823299.781 3198230.577,823299.781 3197981.749,823039.965 3197981.749,823039.965 3198223.019,822679.619 3198223.019,822679.619 3198979.287,821830.209
  Top Layer region: 4.873,-7.189 4.732,-7.118 4.742,-6.93 4.867,-6.728 5.072,-6.614 5.255,-6.643 5.292,-6.816 5.245,-6.96 5.156,-7.074 5.03,-7.152 hole: 3183436.525,821627.266 3184576.531,822157.87 3184576.531,822157.87 3185163.673,823231.37 3185163.673,823231.37 3184599.229,823304.143 3184599.229,823304.143 3183656.156,822574.909 3183656.156,822574.909 3183220.971,821940.183 3183220.971,821940.183 3183436.525,821627.266
  Top Layer region: 10.82,-6.774 10.708,-6.887 10.575,-6.8 10.645,-6.649 10.684,-6.633 10.729,-6.643
  Top Layer region: 0.76,-6.886 0.673,-6.785 0.724,-6.657 0.806,-6.64 0.879,-6.674 0.894,-6.821
  Top Layer region: 5.839,-6.849 5.745,-6.88 5.639,-6.788 5.693,-6.656 5.813,-6.655 5.871,-6.76
  Top Layer region: 4.389,-6.778 4.255,-6.812 4.199,-6.719 4.242,-6.624 4.315,-6.614 4.383,-6.642
  Top Layer region: 7.282,-6.79 7.147,-6.798 7.104,-6.675 7.134,-6.631 7.178,-6.611 7.306,-6.665
  Top Layer region: 10.447,-5.631 10.3,-5.621 10.291,-5.425 10.286,-5.003 10.286,-4.577 10.293,-4.368 10.427,-4.357 10.721,-4.352 11.024,-4.354 11.186,-4.364 11.375,-4.468 11.493,-4.642 11.509,-4.767 11.515,-4.98 11.511,-5.195 11.496,-5.323 11.391,-5.495 11.221,-5.606 11.057,-5.621 10.749,-5.63 hole: 3240049.547,841521.294 3240049.547,837249.072 3240049.547,837249.072 3241987.06,837249.072 3241987.06,837249.072 3244228.86,837357.443 3244228.86,837357.443 3245452.437,837897.908 3245452.437,837897.908 3245962.863,839193.495 3245962.863,839193.495 3246065.212,841567.232 3246065.212,841567.232 3246065.212,844185.691 3246065.212,844185.691 3245810.597,844618.986 3245810.597,844618.986 3245274.44,845256.222 3245274.44,845256.222 3244572.959,845662.428 3244572.959,845662.428 3243826.888,845758.073 3243826.888,845758.073 3242138.957,845789.483 3242138.957,845789.483 3240049.547,845793.516 3240049.547,845793.516 3240049.547,841521.294
  Top Layer region: 6.251,-5.621 6.104,-5.631 5.803,-5.63 5.495,-5.621 5.33,-5.606 5.161,-5.494 5.055,-5.323 5.039,-5.193 5.035,-4.981 5.043,-4.77 5.061,-4.643 5.163,-4.479 5.326,-4.376 5.378,-4.354 5.816,-4.354 6.182,-4.356 6.259,-4.368 6.264,-4.468 6.252,-4.554 6.224,-4.559 6.152,-4.562 6.035,-4.565 5.874,-4.567 5.551,-4.572 5.469,-4.59 5.382,-4.671 5.349,-4.805 5.343,-4.887 5.798,-4.887 6.179,-4.889 6.259,-4.901 6.264,-5 6.253,-5.087 6.225,-5.092 6.146,-5.095 6.006,-5.097 5.793,-5.098 5.343,-5.098 5.349,-5.175 5.357,-5.249 5.374,-5.306 5.404,-5.349 5.451,-5.38 5.52,-5.4 5.615,-5.412 5.741,-5.418 5.902,-5.419 6.195,-5.422 6.259,-5.434 6.265,-5.535
  Top Layer region: 9.117,-5.631 8.976,-5.62 8.968,-5.423 8.964,-5.001 8.964,-4.575 8.97,-4.368 9.113,-4.357 9.426,-4.352 9.748,-4.355 9.919,-4.364 10.05,-4.426 10.146,-4.515 10.204,-4.628 10.224,-4.765 10.189,-4.954 10.047,-5.118 10.022,-5.139 10.103,-5.326 10.212,-5.606 10.076,-5.631 9.937,-5.624 9.902,-5.586 9.885,-5.546 9.863,-5.495 9.845,-5.453 9.837,-5.433 9.826,-5.406 9.8,-5.349 9.774,-5.292 9.764,-5.265 9.759,-5.251 9.748,-5.225 9.732,-5.19 9.509,-5.19 9.286,-5.19 9.286,-5.401 9.283,-5.582 9.268,-5.621 hole: 3226962.033,841705.046 3229160.377,841680.377 3229160.377,841680.377 3231010.556,841688.229 3231010.556,841688.229 3231783.225,841796.747 3231783.225,841796.747 3233195.982,843675.31 3233195.982,843675.31 3231947.421,845651.045 3231947.421,845651.045 3231216.023,845765.812 3231216.023,845765.812 3229259.282,845793.516 3229259.282,845793.516 3226912.594,845793.516 3226912.594,845793.516 3226937.318,843749.281 3226937.318,843749.281 3226962.033,841705.046
  Top Layer region: 6.94,-5.631 6.797,-5.624 6.761,-5.586 6.751,-5.557 6.742,-5.534 6.716,-5.467 6.69,-5.392 6.678,-5.357 6.669,-5.332 6.643,-5.266 6.617,-5.19 6.605,-5.155 6.595,-5.13 6.57,-5.064 6.543,-4.988 6.531,-4.953 6.522,-4.928 6.494,-4.854 6.465,-4.772 6.455,-4.743 6.446,-4.726 6.441,-4.714 6.439,-4.698 6.437,-4.682 6.433,-4.672 6.413,-4.628 6.378,-4.528 6.366,-4.494 6.356,-4.469 6.326,-4.386 6.329,-4.353 6.378,-4.347 6.476,-4.345 6.609,-4.352 6.643,-4.395 6.672,-4.48 6.705,-4.57 6.731,-4.638 6.757,-4.712 6.769,-4.747 6.778,-4.772 6.804,-4.838 6.831,-4.914 6.842,-4.949 6.852,-4.974 6.882,-5.053 6.909,-5.132 6.927,-5.169 6.945,-5.146 6.955,-5.123 6.963,-5.102 6.972,-5.077 6.984,-5.043 7.01,-4.967 7.036,-4.9 7.046,-4.875 7.057,-4.841 7.074,-4.793 7.096,-4.735 7.118,-4.675 7.139,-4.62 7.154,-4.579 7.165,-4.551 7.199,-4.457 7.226,-4.375 7.258,-4.35 7.385,-4.345 7.528,-4.355 7.534,-4.396 7.525,-4.412 7.515,-4.441 7.486,-4.523 7.458,-4.597 7.448,-4.622 7.437,-4.657 7.41,-4.733 7.384,-4.799 7.375,-4.824 7.363,-4.859 7.337,-4.935 7.311,-5.001 7.301,-5.027 7.29,-5.061 7.263,-5.137 7.237,-5.204 7.228,-5.229 7.216,-5.263 7.19,-5.338 7.164,-5.406 7.131,-5.495 7.103,-5.58 7.068,-5.623
  Top Layer region: 8.907,-5.621 8.762,-5.631 8.63,-5.623 8.589,-5.568 8.569,-5.52 8.55,-5.477 8.538,-5.448 8.533,-5.434 8.526,-5.416 8.511,-5.381 8.486,-5.322 8.455,-5.249 8.426,-5.18 8.403,-5.128 8.391,-5.099 8.386,-5.084 8.38,-5.067 8.364,-5.032 8.339,-4.973 8.308,-4.9 8.279,-4.831 8.258,-4.781 8.244,-4.749 8.235,-4.724 8.207,-4.717 8.133,-4.882 8.103,-4.955 8.077,-5.013 8.062,-5.049 8.055,-5.066 8.048,-5.086 8.029,-5.128 8.007,-5.178 7.991,-5.217 7.98,-5.243 7.971,-5.258 7.966,-5.268 7.963,-5.279 7.955,-5.304 7.936,-5.347 7.926,-5.411 8.09,-5.419 8.262,-5.419 8.306,-5.512 8.346,-5.606 8.329,-5.625 8.191,-5.63 7.919,-5.63 7.651,-5.628 7.523,-5.622 7.524,-5.597 7.546,-5.533 7.587,-5.431 7.648,-5.293 7.663,-5.257 7.67,-5.24 7.677,-5.22 7.695,-5.179 7.717,-5.128 7.734,-5.089 7.745,-5.063 7.754,-5.048 7.759,-5.038 7.761,-5.028 7.769,-5.002 7.788,-4.958 7.817,-4.893 7.849,-4.818 7.879,-4.745 7.905,-4.686 7.92,-4.651 7.927,-4.634 7.935,-4.613 7.954,-4.57 7.974,-4.526 7.982,-4.505 7.987,-4.489 8.001,-4.457 8.018,-4.417 8.033,-4.383 8.046,-4.353 8.217,-4.356 8.388,-4.358 8.452,-4.51 8.503,-4.628 8.534,-4.7 8.546,-4.729 8.551,-4.744 8.559,-4.765 8.579,-4.808 8.598,-4.852 8.606,-4.873 8.613,-4.89 8.628,-4.925 8.662,-5.003 8.712,-5.121 8.76,-5.236 8.791,-5.307 8.803,-5.336 8.808,-5.35 8.816,-5.371 8.836,-5.415 8.855,-5.459 8.863,-5.479 8.872,-5.5 8.891,-5.543
  Top Layer region: 4.965,-5.621 4.86,-5.63 4.648,-5.63 4.43,-5.622 4.308,-5.608 4.139,-5.501 4.029,-5.332 4.016,-5.172 4.006,-4.861 4.003,-4.546 4.009,-4.376 4.015,-4.353 4.168,-4.356 4.322,-4.358 4.326,-4.814 4.331,-5.269 4.356,-5.307 4.405,-5.367 4.47,-5.401 4.575,-5.416 4.745,-5.419 4.93,-5.422 4.973,-5.434 4.979,-5.535
  Top Layer region: 0.504,-5.63 0.172,-5.629 0.014,-5.621 0.005,-5.425 0,-5.003 0,-4.577 0.006,-4.368 0.011,-4.364 0.023,-4.36 0.047,-4.358 0.088,-4.356 0.147,-4.355 0.231,-4.355 0.343,-4.355 0.486,-4.356 0.96,-4.358 1.016,-4.385 1.114,-4.454 1.182,-4.539 1.221,-4.63 1.226,-4.725 1.211,-4.846 1.161,-4.94 1.138,-4.97 1.172,-5.008 1.256,-5.173 1.253,-5.346 1.169,-5.5 1.011,-5.611 0.84,-5.623 hole: 3137186.279,838856.898 3137186.279,837249.072 3137186.279,837249.072 3139688.979,837251.094 3139688.979,837251.094 3142301.391,837348.439 3142301.391,837348.439 3143225.693,837926.913 3143225.693,837926.913 3143456.385,839381.971 3143456.385,839381.971 3142427.906,840403.681 3142427.906,840403.681 3141487.372,840446.792 3141487.372,840446.792 3139654.538,840464.723 3139654.538,840464.723 3137186.279,840464.723 3137186.279,840464.723 3137186.279,838856.898 hole: 3137186.279,844185.691 3137186.279,842577.865 3137186.279,842577.865 3139551.215,842579.887 3139551.215,842579.887 3141584.814,842609.898 3141584.814,842609.898 3142290.74,842752.089 3142290.74,842752.089 3143219.21,844179.676 3143219.21,844179.676 3142320.368,845660.398 3142320.368,845660.398 3141626.463,845766.871 3141626.463,845766.871 3139624.662,845793.516 3139624.662,845793.516 3137186.279,845793.516 3137186.279,845793.516 3137186.279,844185.691
  Top Layer region: 1.576,-5.626 1.536,-5.605 1.452,-5.542 1.392,-5.459 1.365,-5.406 1.365,-4.991 1.367,-4.654 1.377,-4.55 1.389,-4.525 1.4,-4.503 1.451,-4.436 1.528,-4.382 1.585,-4.354 1.978,-4.354 2.26,-4.356 2.386,-4.362 2.408,-4.373 2.438,-4.387 2.506,-4.441 2.565,-4.52 2.586,-4.56 2.586,-4.988 2.586,-5.415 2.563,-5.461 2.503,-5.543 2.421,-5.603 2.375,-5.626 1.975,-5.626 hole: 3153855.639,837252.6 3154860.233,837253.507 3154860.233,837253.507 3155605.43,837294.565 3155605.43,837294.565 3156129.896,837432.325 3156129.896,837432.325 3156472.297,837723.343 3156472.297,837723.343 3156671.3,838224.171 3156671.3,838224.171 3156765.572,838991.363 3156765.572,838991.363 3156793.779,840081.473 3156793.779,840081.473 3156794.589,841551.053 3156794.589,841551.053 3156794.589,844920.697 3156794.589,844920.697 3156574.287,845229.684 3156574.287,845229.684 3156329.157,845485.343 3156329.157,845485.343 3156049.152,845666.094 3156049.152,845666.094 3155380.887,845765.471 3155380.887,845765.471 3153788.272,845793.516 3153788.272,845793.516 3151767.331,845706.004 3151767.331,845706.004 3151036.9,845198.566 3151036.9,845198.566 3150824.846,844925.19 3150824.846,844925.19 3150824.846,841569.474 3150824.846,841569.474 3150824.846,838213.768 3150824.846,838213.768 3151045.368,837904.468 3151045.368,837904.468 3151827.152,837363.018 3151827.152,837363.018 3153855.639,837252.6
  Top Layer region: 3.755,-5.595 3.697,-5.626 3.298,-5.626 2.898,-5.626 2.858,-5.605 2.775,-5.542 2.714,-5.459 2.687,-5.406 2.684,-4.901 2.684,-4.538 2.687,-4.375 2.692,-4.353 2.846,-4.356 2.999,-4.358 3.004,-4.845 3.009,-5.196 3.037,-5.365 3.124,-5.417 3.305,-5.419 3.502,-5.407 3.58,-5.347 3.601,-5.316 3.601,-4.846 3.614,-4.391 3.767,-4.356 3.918,-4.358 3.921,-4.841 3.899,-5.421
  Top Layer region: 3.143,-3.398 3.05,-3.391 2.997,-3.328 2.987,-3.214 3.021,-3.054 3.089,-2.915 3.194,-2.791 3.321,-2.697 3.456,-2.646 3.517,-2.653 3.475,-2.73 3.441,-2.776 3.422,-2.803 3.394,-2.841 3.34,-2.912 3.207,-3.102 3.211,-3.165 3.264,-3.159 3.338,-3.106 3.435,-3.005 3.555,-2.852 3.634,-2.778 3.651,-2.893 3.615,-3.071 3.515,-3.217 3.356,-3.328
  Top Layer region: 8.495,-3.318 8.386,-3.395 8.216,-3.357 8.069,-3.279 7.948,-3.164 7.86,-3.016 7.85,-2.882 7.859,-2.767 7.891,-2.786 7.981,-2.893 8.188,-3.127 8.28,-3.165 8.298,-3.103 8.221,-2.985 8.066,-2.78 7.991,-2.658 8.051,-2.649 8.156,-2.685 8.185,-2.701 8.209,-2.714 8.383,-2.883 8.486,-3.116
  Top Layer region: 5.255,-3.36 5.129,-3.393 4.939,-3.331 4.743,-3.082 4.794,-2.84 4.903,-2.816 5.035,-2.854 5.161,-2.94 5.252,-3.06 5.302,-3.244 hole: 3184802.255,859391.126 3185037.517,860120.259 3185037.517,860120.259 3184099.249,861190.908 3184099.249,861190.908 3183403.282,861275.976 3183403.282,861275.976 3183294.436,860761.122 3183294.436,860761.122 3184016.963,859960.953 3184016.963,859960.953 3184802.255,859391.126
  Top Layer region: 2.02,-3.38 1.938,-3.356 1.901,-3.291 1.903,-3.198 1.939,-3.088 2.003,-2.973 2.09,-2.865 2.196,-2.776 2.314,-2.718 2.518,-2.724 2.532,-2.962 2.467,-3.127 2.35,-3.26 2.196,-3.348 hole: 3155313.17,860362.092 3155589.757,859850.505 3155589.757,859850.505 3156934.376,860918.434 3156934.376,860918.434 3157611.774,862306.463 3157611.774,862306.463 3157198.41,862422.813 3157198.41,862422.813 3156252.537,861611.12 3156252.537,861611.12 3155313.17,860362.092
  Top Layer region: 6.739,-3.144 6.463,-3.378 6.218,-3.334 6.203,-3.189 6.258,-3.041 6.369,-2.913 6.522,-2.831 6.665,-2.819 6.755,-2.877 6.783,-2.989 hole: 3198163.689,859489.268 3199248.289,859881.733 3199248.289,859881.733 3199883.939,861175.803 3199883.939,861175.803 3199756.386,861283.668 3199756.386,861283.668 3199481.137,861315.996 3199481.137,861315.996 3198454.95,860583.171 3198454.95,860583.171 3198163.689,859489.268
  Top Layer region: 9.568,-3.335 9.447,-3.372 9.243,-3.31 9.082,-3.184 8.974,-3.011 8.941,-2.84 9.001,-2.72 9.122,-2.702 9.277,-2.756 9.428,-2.862 9.533,-2.999 9.6,-3.208 hole: 3226378.84,860748.534 3227896.252,859872.867 3227896.252,859872.867 3227792.71,860703.507 3227792.71,860703.507 3226711.91,861852.165 3226711.91,861852.165 3225929.185,862347.171 3225929.185,862347.171 3225499.051,862433.545 3225499.051,862433.545 3226378.84,860748.534
  Top Layer region: 155 vertices and 0 holes, not listed, extent 1.255,-3.37 10.228,0
  Top Layer region: 5.763,-3.361 5.641,-3.283 5.685,-3.144 5.763,-3.121 5.84,-3.149 5.87,-3.282
  Top Layer region: 7.312,-3.291 7.207,-3.356 7.101,-3.291 7.138,-3.173 7.212,-3.149 7.286,-3.177
  Top Layer region: 0.829,-3.355 0.689,-3.295 0.675,-3.2 0.728,-3.123 0.85,-3.121 0.914,-3.226
  Top Layer region: 10.82,-3.226 10.734,-3.348 10.595,-3.311 10.574,-3.19 10.671,-3.104 10.769,-3.131
  Top Layer region: 4.361,-3.343 4.213,-3.315 4.247,-3.161 4.299,-3.142 4.354,-3.156 4.409,-3.25
  Top Layer region: 3.958,-2.868 3.875,-2.9 3.817,-2.806 3.852,-2.609 3.949,-2.403 4.078,-2.281 4.124,-2.27 4.158,-2.29 4.183,-2.311 4.131,-2.407 4.057,-2.562 4.014,-2.703
  Top Layer region: 7.662,-2.873 7.561,-2.89 7.501,-2.758 7.462,-2.601 7.389,-2.418 7.342,-2.311 7.369,-2.277 7.49,-2.318 7.613,-2.498 7.686,-2.717
  Top Layer region: 7.173,-2.823 7.112,-2.888 7.034,-2.86 6.99,-2.789 6.988,-2.778 6.982,-2.768 6.958,-2.702 6.932,-2.608 6.906,-2.512 6.853,-2.334 6.818,-2.201 6.831,-2.153 6.897,-2.15 6.979,-2.235 7.06,-2.384 7.125,-2.576
  Top Layer region: 4.498,-2.825 4.407,-2.884 4.335,-2.836 4.355,-2.668 4.46,-2.352 4.579,-2.177 4.68,-2.148 4.67,-2.291 4.625,-2.426 4.578,-2.594
  Top Layer region: 5.58,-2.736 5.451,-2.81 5.377,-2.682 5.388,-2.459 5.403,-2.414 5.42,-2.36 5.477,-2.223 5.549,-2.119 5.598,-2.078 5.645,-2.095 5.682,-2.114 5.682,-2.272 5.685,-2.415 5.707,-2.478 5.756,-2.531 5.798,-2.501 5.825,-2.4 5.831,-2.24 5.827,-2.111 5.864,-2.093 5.966,-2.132 6.063,-2.294 6.125,-2.508 6.123,-2.705 6.087,-2.789 6.033,-2.809 5.95,-2.762 5.824,-2.646 5.747,-2.568 5.723,-2.6
  Top Layer region: 6.559,-2.571 6.33,-2.502 6.233,-2.369 6.214,-2.265 6.341,-2.271 6.501,-2.369
  Top Layer region: 3.141,-2.567 3.093,-2.562 2.964,-2.535 2.861,-2.497 2.764,-2.43 2.675,-2.334 2.596,-2.211 2.589,-2.091 2.779,-2.024 2.971,-2.013 3.152,-2.041 3.292,-2.102 3.362,-2.186 3.35,-2.252 3.215,-2.241 2.952,-2.202 2.856,-2.226 2.86,-2.268 2.921,-2.305 3.049,-2.34 3.257,-2.378 3.448,-2.411 3.49,-2.433 3.502,-2.47 3.473,-2.501 3.346,-2.541 3.207,-2.562 3.163,-2.564
  Top Layer region: 5.306,-2.304 5.096,-2.557 4.933,-2.525 5.007,-2.369 5.168,-2.267 5.207,-2.257 5.236,-2.249 5.304,-2.245
  Top Layer region: 8.653,-2.477 8.423,-2.554 8.184,-2.548 7.985,-2.459 8.207,-2.382 8.502,-2.327 8.625,-2.284 8.661,-2.23 8.608,-2.206 8.469,-2.21 8.248,-2.245 8.142,-2.237 8.146,-2.174 8.235,-2.093 8.385,-2.034 8.444,-2.021 8.487,-2.012 8.787,-2.038 8.943,-2.152 8.839,-2.337
  Top Layer region: 2.336,-2.479 2.244,-2.407 2.29,-2.296 2.385,-2.284 2.436,-2.346 2.415,-2.446
  Top Layer region: 9.235,-2.45 9.092,-2.453 9.063,-2.38 9.092,-2.306 9.123,-2.282 9.167,-2.277 9.211,-2.282 9.241,-2.306
  Top Layer region: 3.807,-2.301 3.721,-2.351 3.552,-2.296 3.523,-2.187 3.54,-2.169 3.57,-2.175 3.66,-2.202 3.766,-2.234
  Top Layer region: 7.998,-2.225 7.894,-2.337 7.723,-2.331 7.695,-2.27 7.826,-2.21 7.89,-2.193 7.945,-2.188 7.996,-2.19
  Top Layer region: 3.987,-2.127 3.743,-2.064 3.56,-1.912 3.437,-1.707 3.398,-1.509 3.466,-1.377 3.546,-1.361 3.662,-1.38 3.796,-1.427 3.929,-1.499 4.085,-1.637 4.212,-1.813 4.284,-1.978 4.272,-2.085 4.203,-2.11 4.125,-2.025 4.01,-1.889 3.851,-1.739 3.704,-1.622 3.623,-1.589 3.609,-1.624 3.635,-1.681 3.707,-1.769 3.83,-1.896
  Top Layer region: 7.275,-2.115 7.216,-2.067 7.232,-1.943 7.339,-1.731 7.484,-1.564 7.666,-1.442 7.885,-1.365 8.044,-1.375 8.092,-1.518 8.061,-1.716 7.972,-1.888 7.834,-2.022 7.656,-2.107 7.509,-2.102 7.641,-1.933 7.857,-1.701 7.884,-1.582 7.812,-1.604 7.696,-1.691 7.557,-1.823 7.42,-1.979 7.322,-2.095
  Top Layer region: 6.562,-2.057 6.369,-2.108 6.189,-2.085 6.042,-1.987 6.039,-1.912 6.064,-1.83 6.18,-1.773 6.342,-1.726 6.636,-1.792 6.744,-1.933
  Top Layer region: 5.428,-2.014 5.238,-2.105 5.021,-2.093 4.849,-1.999 4.74,-1.901 4.857,-1.806 5.024,-1.723 5.17,-1.725 5.396,-1.794 5.449,-1.836 5.472,-1.917 5.477,-1.971
  Top Layer region: 5.819,-1.961 5.668,-1.956 5.594,-1.809 5.626,-1.713 5.701,-1.653 5.897,-1.747
  Top Layer region: 8.566,-1.683 8.479,-1.763 8.372,-1.713 8.366,-1.636 8.427,-1.571 8.527,-1.583
  Top Layer region: 3.142,-1.653 3.049,-1.759 2.942,-1.701 2.975,-1.581 3.002,-1.566 3.033,-1.561
  Top Layer region: 5.498,-1.643 5.466,-1.669 5.374,-1.645 5.294,-1.619 5.213,-1.593 5.052,-1.491 4.959,-1.3 4.942,-1.194 4.962,-1.152 4.982,-1.148 5.002,-1.144 5.159,-1.134 5.306,-1.176 5.431,-1.266 5.524,-1.397 5.572,-1.517 5.545,-1.578 5.518,-1.612
  Top Layer region: 6.13,-1.644 6.04,-1.667 5.981,-1.612 5.938,-1.545 5.956,-1.467 6.088,-1.255 6.296,-1.152 6.514,-1.141 6.559,-1.236 6.467,-1.476 6.269,-1.597 6.202,-1.619
  Top Layer region: 4.73,-1.522 4.647,-1.592 4.494,-1.571 4.328,-1.479 4.208,-1.337 4.147,-1.093 4.2,-0.932 4.374,-0.939 4.582,-1.065 4.708,-1.282 hole: 3178615.634,877986.62 3179163.548,877582.523 3179163.548,877582.523 3179420.371,877840.755 3179420.371,877840.755 3179450.16,878233.417 3179450.16,878233.417 3179373.667,878385.35 3179373.667,878385.35 3179341.85,878507.013 3179341.85,878507.013 3178894.594,879181.313 3178894.594,879181.313 3178175.013,879906.556 3178175.013,879906.556 3177379.136,879900.589 3177379.136,879900.589 3177899.808,878685.032 3177899.808,878685.032 3178615.634,877986.62
  Top Layer region: 6.999,-1.576 6.816,-1.585 6.777,-1.415 6.818,-1.24 6.898,-1.098 7.015,-0.994 7.166,-0.93 7.315,-0.94 7.358,-1.086 7.337,-1.253 7.271,-1.389 7.159,-1.496 hole: 3203744.324,877983.738 3204007.939,877582.523 3204007.939,877582.523 3205096.133,878420.486 3205096.133,878420.486 3205792.405,879730.137 3205792.405,879730.137 3205177.908,879955.656 3205177.908,879955.656 3203933.537,878698.942 3203933.537,878698.942 3203744.324,877983.738
  Top Layer region: 5.818,-1.435 5.756,-1.497 5.695,-1.416 5.659,-1.33 5.566,-1.176 5.532,-1.07 5.546,-0.946 5.605,-0.811 5.707,-0.676 5.77,-0.655 5.865,-0.757 5.971,-0.989 5.916,-1.214 5.866,-1.312
  Top Layer region: 5.068,-0.907 4.934,-0.917 4.883,-0.832 4.924,-0.739 5.024,-0.718 5.103,-0.783
  Top Layer region: 6.61,-0.791 6.559,-0.915 6.417,-0.891 6.426,-0.746 6.46,-0.721 6.502,-0.715
IMPORTED_IMAGE#2 [mm]
LED-SMD_L3.2-W1.3-RD-EH2.1 [mm]
  rect 1.07x1.25 smd: 1(1.58,0) 2(-1.58,0)
  Multi-Layer board cut-out: -0.876,0.657 -0.876,0.658 -0.867,0.703 -0.841,0.741 -0.803,0.767 -0.758,0.776 -0.758,0.776 0.763,0.776 0.807,0.767 0.844,0.743 0.868,0.706 0.877,0.662 0.877,0.662 0.877,-0.67 0.869,-0.711 0.846,-0.745 0.812,-0.768 0.771,-0.776 0.771,-0.776 -0.76,-0.776 -0.805,-0.767 -0.843,-0.742 -0.868,-0.704 -0.877,-0.659 -0.877,-0.659
  Multi-Layer keep-out region: -0.876,0.657 -0.876,0.658 -0.867,0.703 -0.841,0.741 -0.803,0.767 -0.758,0.776 -0.758,0.776 0.763,0.776 0.807,0.767 0.844,0.743 0.868,0.706 0.877,0.662 0.877,0.662 0.877,-0.67 0.869,-0.711 0.846,-0.745 0.812,-0.768 0.771,-0.776 0.771,-0.776 -0.76,-0.776 -0.805,-0.767 -0.843,-0.742 -0.868,-0.704 -0.877,-0.659 -0.877,-0.659
  silkscreen extent -2.4,-1 2.4,1
PCB卫星轴-7U [mm]
  Multi-Layer board cut-out: -55.118,8.255 -55.319,9.137 -55.883,9.844 -56.698,10.236 -57.602,10.236 -58.417,9.844 -58.981,9.137 -59.182,8.255 -59.182,8.255 -58.981,7.373 -58.417,6.666 -57.602,6.274 -56.698,6.274 -55.883,6.666 -55.319,7.373 -55.118,8.255
  Multi-Layer board cut-out: 59.182,8.255 58.981,9.137 58.417,9.844 57.602,10.236 56.698,10.236 55.883,9.844 55.319,9.137 55.118,8.255 55.118,8.255 55.319,7.373 55.883,6.666 56.698,6.274 57.602,6.274 58.417,6.666 58.981,7.373 59.182,8.255
  Multi-Layer board cut-out: 58.674,-6.985 58.523,-6.324 58.1,-5.793 57.489,-5.499 56.811,-5.499 56.2,-5.793 55.777,-6.324 55.626,-6.985 55.626,-6.985 55.777,-7.646 56.2,-8.176 56.811,-8.471 57.489,-8.471 58.1,-8.177 58.523,-7.646 58.674,-6.985
  Multi-Layer board cut-out: -55.626,-6.985 -55.777,-6.324 -56.2,-5.793 -56.811,-5.499 -57.489,-5.499 -58.1,-5.793 -58.523,-6.324 -58.674,-6.985 -58.674,-6.985 -58.523,-7.646 -58.1,-8.176 -57.489,-8.471 -56.811,-8.471 -56.2,-8.177 -55.777,-7.646 -55.626,-6.985
  Multi-Layer keep-out region: -55.118,8.255 -55.319,9.137 -55.883,9.844 -56.698,10.236 -57.602,10.236 -58.417,9.844 -58.981,9.137 -59.182,8.255 -59.182,8.255 -58.981,7.373 -58.417,6.666 -57.602,6.274 -56.698,6.274 -55.883,6.666 -55.319,7.373 -55.118,8.255
  Multi-Layer keep-out region: 59.182,8.255 58.981,9.137 58.417,9.844 57.602,10.236 56.698,10.236 55.883,9.844 55.319,9.137 55.118,8.255 55.118,8.255 55.319,7.373 55.883,6.666 56.698,6.274 57.602,6.274 58.417,6.666 58.981,7.373 59.182,8.255
  Multi-Layer keep-out region: 58.674,-6.985 58.523,-6.324 58.1,-5.793 57.489,-5.499 56.811,-5.499 56.2,-5.793 55.777,-6.324 55.626,-6.985 55.626,-6.985 55.777,-7.646 56.2,-8.176 56.811,-8.471 57.489,-8.471 58.1,-8.177 58.523,-7.646 58.674,-6.985
  Multi-Layer keep-out region: -55.626,-6.985 -55.777,-6.324 -56.2,-5.793 -56.811,-5.499 -57.489,-5.499 -58.1,-5.793 -58.523,-6.324 -58.674,-6.985 -58.674,-6.985 -58.523,-7.646 -58.1,-8.176 -57.489,-8.471 -56.811,-8.471 -56.2,-8.177 -55.777,-7.646 -55.626,-6.985
R0805 [mm]
  rect 1.133x1.377 smd: 1(-1,0) 2(1,0)
  silkscreen extent -1.76,-0.92 1.76,0.92
SOD-123_L2.8-W1.8-LS3.7-RD [mm]
  rect 0.95x1.15 smd: 1(-1.692,0) 2(1.692,0)
  silkscreen extent -1.63,-0.94 1.41,0.94
SOD-123F_L2.8-W1.8-LS3.7-RD [mm]
  rect 1x1.2 smd: 1(-1.55,0) 2(1.55,0)
  silkscreen extent -1.52,-0.93 1.49,0.95
SOT-23-3_L2.9-W1.6-P1.90-LS2.8-BR [mm]
  rect 1.07x0.6 smd: 1(1.235,-0.95) 2(1.235,0.95) 3(-1.235,0)
  silkscreen extent -0.88,-1.54 0.88,1.54
SOT-23-6_L2.9-W1.6-P0.95-LS2.8-BR [mm]
  rect 1x0.55 smd: 1(1.4,-0.95) 2(1.4,0) 3(1.4,0.95) 4(-1.4,0.95) 5(-1.4,0) 6(-1.4,-0.95)
  silkscreen extent -0.9,-1.78 1.52,1.55
SW-SMD_L3.9-W3.0-P4.45 [mm]
  rect 1.35x2 smd: 1(-2.25,0) 2(2.25,0)
  silkscreen extent -2,-1.45 2,1.45
TSSOP-20_L6.5-W4.4-P0.65-LS6.4-BL [mm]
  rect 0.4x1.494 smd: 1(-2.925,-3.001) 2(-2.275,-3.001) 3(-1.625,-3.001) 4(-0.975,-3.001) 5(-0.325,-3.001) 6(0.324,-3.001) 7(0.975,-3.001) 8(1.625,-3.001) 9(2.275,-3.001) 10(2.925,-3.001) 11(2.925,3.001) 12(2.275,3.001) 13(1.625,3.001) 14(0.975,3.001) 15(0.325,3.001) 16(-0.325,3.001) 17(-0.975,3.001) 18(-1.625,2.996) 19(-2.275,2.996) 20(-2.925,3.001)
  silkscreen extent -4.15,-3.5 3.3,2.1
凯华轴座无灯#1 [mm]
  rect 2.54x2.54 smd far side: COL(-7.6,2.59) ROW(6.35,5.08)
  Multi-Layer board cut-out: -2.285,2.565 -2.49,3.31 -3.038,3.854 -3.785,4.053 -4.531,3.854 -5.079,3.31 -5.284,2.565 -5.284,2.565 -5.079,1.821 -4.531,1.277 -3.785,1.078 -3.038,1.277 -2.49,1.821 -2.285,2.565
  Multi-Layer board cut-out: 4.116,4.953 3.911,5.698 3.363,6.242 2.616,6.441 1.87,6.242 1.321,5.698 1.116,4.953 1.116,4.953 1.321,4.208 1.87,3.664 2.616,3.465 3.363,3.664 3.911,4.208 4.116,4.953
  Multi-Layer board cut-out: 2,0 1.802,0.868 1.247,1.564 0.445,1.95 -0.445,1.95 -1.247,1.564 -1.802,0.868 -2,0 -2,0 -1.802,-0.868 -1.247,-1.564 -0.445,-1.95 0.445,-1.95 1.247,-1.564 1.802,-0.868 2,0
  Multi-Layer board cut-out: -4.028,-0.025 -4.157,0.448 -4.505,0.793 -4.978,0.92 -5.452,0.793 -5.799,0.447 -5.928,-0.025 -5.928,-0.025 -5.799,-0.498 -5.452,-0.844 -4.978,-0.971 -4.505,-0.844 -4.157,-0.498 -4.028,-0.025
  Multi-Layer board cut-out: 5.979,-0.025 5.85,0.448 5.503,0.793 5.029,0.92 4.556,0.793 4.208,0.447 4.079,-0.025 4.079,-0.025 4.208,-0.498 4.556,-0.844 5.029,-0.971 5.503,-0.844 5.85,-0.498 5.979,-0.025
  Multi-Layer keep-out region: -2.285,2.565 -2.49,3.31 -3.038,3.854 -3.785,4.053 -4.531,3.854 -5.079,3.31 -5.284,2.565 -5.284,2.565 -5.079,1.821 -4.531,1.277 -3.785,1.078 -3.038,1.277 -2.49,1.821 -2.285,2.565
  Multi-Layer keep-out region: 4.116,4.953 3.911,5.698 3.363,6.242 2.616,6.441 1.87,6.242 1.321,5.698 1.116,4.953 1.116,4.953 1.321,4.208 1.87,3.664 2.616,3.465 3.363,3.664 3.911,4.208 4.116,4.953
  Multi-Layer keep-out region: 2,0 1.802,0.868 1.247,1.564 0.445,1.95 -0.445,1.95 -1.247,1.564 -1.802,0.868 -2,0 -2,0 -1.802,-0.868 -1.247,-1.564 -0.445,-1.95 0.445,-1.95 1.247,-1.564 1.802,-0.868 2,0
  Multi-Layer keep-out region: -4.028,-0.025 -4.157,0.448 -4.505,0.793 -4.978,0.92 -5.452,0.793 -5.799,0.447 -5.928,-0.025 -5.928,-0.025 -5.799,-0.498 -5.452,-0.844 -4.978,-0.971 -4.505,-0.844 -4.157,-0.498 -4.028,-0.025
  Multi-Layer keep-out region: 5.979,-0.025 5.85,0.448 5.503,0.793 5.029,0.92 4.556,0.793 4.208,0.447 4.079,-0.025 4.079,-0.025 4.208,-0.498 4.556,-0.844 5.029,-0.971 5.503,-0.844 5.85,-0.498 5.979,-0.025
